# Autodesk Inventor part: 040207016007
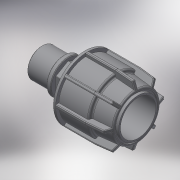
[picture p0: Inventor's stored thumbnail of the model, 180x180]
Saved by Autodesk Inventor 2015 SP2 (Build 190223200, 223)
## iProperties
Created: 2017-08
Part Number: 040207016007
Material: Generic
Description: PLASSON IRRIFIT ADAPTOR 16-3/4"M
Document SubType Name: Modeling
Designer: KIM
Density: 1 g/cm^3
Appearance: Default
Author: KIM
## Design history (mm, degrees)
derived "040207.ipt"
feature "Solid1::040207.ipt"
tag "TaggingFeature1"
body "Solid1"
other parameters: "d5" = 30.7, "d6" = 14.3, "d10" = 34, "d22" = 26.441, "d24" = 1.495, "d25" = 30.6, "d26" = 27.2, "d31" = 0.64, "d49" = 1.7, "d50" = 0, "d58" = 0.32, "d61" = 360 deg, "d77" = 16, "d78" = 5 deg, "d80" = 17.6, "d81" = 32.5, "d82" = 1.95, "d84" = 5 deg, "d85" = 70 deg, "d86" = 32.3, "d87" = 0.325, "d88" = 0, "d89" = 28.9, "d90" = 3.25, "d91" = 0, "d99" = 26.441, "d100" = 17, "d101" = 3.4, "d102" = 65, "d103" = 31.7292, "d104" = 0.52882, "d108" = 0, "d109" = 0.26441, "d112" = 16, "d113" = 24.56, "d_" = 16, "E_" = 34, "H_" = 65, "l_nut" = 30.7, "l_" = 17, "R_" = 26.441
